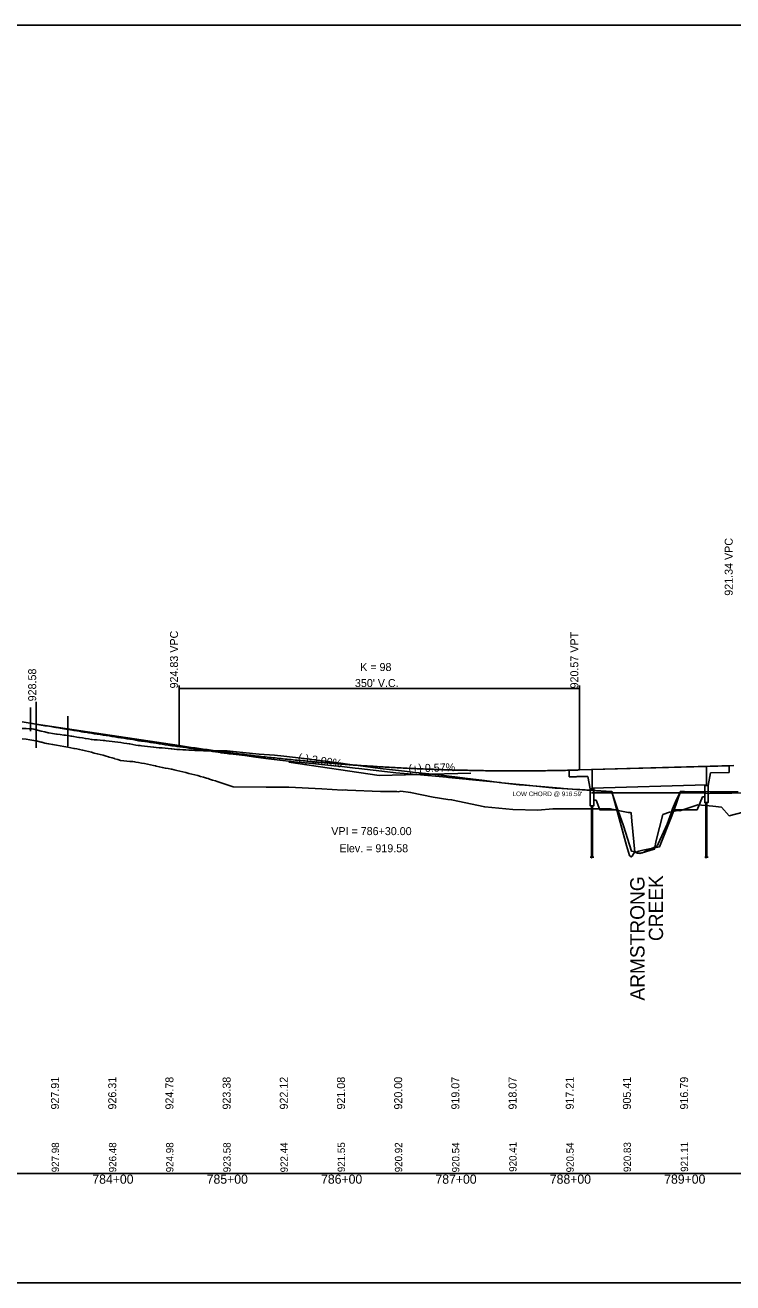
# Model space of a CAD drawing. Extents: x 1558113 to 1562835, y 1129435 to 1135883.
# Drawn here: x 1559817 to 1560436, y 1133348 to 1134448 of the extents above; entities that cross this region are included whole.
import ezdxf

# ---------------------------------------------------------------- set-up
doc = ezdxf.new("R2010")
doc.units = 0
for name, color, linetype in [('BR_CONCRETE', 7, 'Continuous'), ('BR_EXIST_GROUND_LT', 7, 'Continuous'), ('BR_EXIST_GROUND_RT', 7, 'Continuous'), ('BR_GROUND LINES', 7, 'Continuous'), ('BR_USER NOTES', 7, 'Continuous'), ('RD_DDB_GradeTX', 7, 'Continuous'), ('RD_DDB_Profile_EX', 7, 'Continuous'), ('RD_DDB_Profile_Lbl', 7, 'Continuous'), ('RD_DDB_Profile_PR', 7, 'Continuous'), ('RD_DDB_StaTX', 7, 'Continuous'), ('RD_DDB_StripGrade', 7, 'Continuous'), ('RD_DDB_VCLbl', 7, 'Continuous'), ('RD_GPK_Profile_Cell', 7, 'Continuous'), ('RD_SHT_ShtClip', 7, 'Continuous'), ('RD_SHT_TX', 7, 'Continuous')]:
    doc.layers.add(name, color=color, linetype=linetype)

msp = doc.modelspace()

# ---------------------------------------------------------------- linework, layer by layer
at = {"layer": 'BR_CONCRETE'}
for p, q in [((1560292.4, 1133790.6), (1560292.4, 1133796.5)), ((1560301.4, 1133796.7), (1560312.4, 1133797)), ((1560312.4, 1133797), (1560412.4, 1133799.8)), ((1560312.4, 1133780.8), (1560312.4, 1133797)), ((1560412.4, 1133799.8), (1560432.4, 1133800.4)), ((1560412.4, 1133783.6), (1560412.4, 1133799.8)), ((1560413.9, 1133783.2), (1560416.1, 1133794.1)), ((1560416.1, 1133794.1), (1560432.4, 1133794.6)), ((1560432.4, 1133794.6), (1560432.4, 1133800.4)), ((1560301.4, 1133790.9), (1560308.7, 1133791.1)), ((1560310.9, 1133780.3), (1560308.7, 1133791.1)), ((1560312.4, 1133780.8), (1560412.4, 1133783.6)), ((1560311.8, 1133765.3), (1560311.8, 1133720.5)), ((1560312.9, 1133765.3), (1560312.9, 1133720.5)), ((1560411.8, 1133768.2), (1560411.8, 1133720.5)), ((1560412.9, 1133768.2), (1560412.9, 1133720.5))]:
    msp.add_line(p, q, dxfattribs=at)
for points in [[(1560413.9, 1133783.2), (1560410.9, 1133783.2), (1560410.9, 1133768.2), (1560413.9, 1133768.2)], [(1560310.9, 1133780.3), (1560313.9, 1133780.3), (1560313.9, 1133765.3), (1560310.9, 1133765.3)]]:
    msp.add_lwpolyline(points, close=True, dxfattribs=at)
for points in [[(1560310.9, 1133720.5), (1560312, 1133720.5), (1560312, 1133719.8), (1560312.7, 1133721.2), (1560312.7, 1133720.5), (1560313.9, 1133720.5)], [(1560410.9, 1133720.5), (1560412, 1133720.5), (1560412, 1133719.8), (1560412.7, 1133721.2), (1560412.7, 1133720.5), (1560413.9, 1133720.5)]]:
    msp.add_lwpolyline(points, dxfattribs=at)
for points in [[(1560292.4, 1133796.5), (1560295.4, 1133796.5), (1560298.4, 1133796.6), (1560301.4, 1133796.7)], [(1560292.4, 1133790.6), (1560295.4, 1133790.7), (1560298.4, 1133790.8), (1560301.4, 1133790.9)]]:
    msp.add_open_spline(points, degree=2, dxfattribs=at)
at = {"layer": 'BR_EXIST_GROUND_LT'}
msp.add_lwpolyline([(1559814.2, 1133823.9), (1559817.6, 1133823.5), (1559820.9, 1133823.1), (1559824.2, 1133822.6), (1559826.3, 1133822.3), (1559827.5, 1133822), (1559830.8, 1133821.1), (1559831.3, 1133820.9), (1559832.3, 1133820.6), (1559834.1, 1133820.2), (1559835.7, 1133819.8), (1559837.4, 1133819.5), (1559840.8, 1133819), (1559844.1, 1133818.4), (1559847.4, 1133817.8), (1559850.7, 1133817.2), (1559854, 1133816.6), (1559856.6, 1133816.1), (1559859.2, 1133815.6), (1559859.8, 1133815.5), (1559861.8, 1133815.1), (1559864.3, 1133814.6), (1559866.9, 1133814), (1559867.3, 1133813.9), (1559869.5, 1133813.4), (1559872.1, 1133812.8), (1559874.7, 1133812.2), (1559877.2, 1133811.5), (1559879.8, 1133810.9), (1559882.4, 1133810.2), (1559885, 1133809.5), (1559887.6, 1133808.7), (1559889.7, 1133808.1), (1559890.1, 1133808), (1559892.7, 1133807.2), (1559895, 1133806.6), (1559895.3, 1133806.5), (1559897.9, 1133805.7), (1559900, 1133805), (1559900.5, 1133804.9), (1559903.1, 1133804.7), (1559905.6, 1133804.5), (1559908.2, 1133804.2), (1559910.8, 1133804), (1559912.4, 1133803.8), (1559913.4, 1133803.6), (1559916, 1133803.2), (1559918.5, 1133802.7), (1559921.1, 1133802.2), (1559923.7, 1133801.7), (1559926.3, 1133801.2), (1559928.9, 1133800.6), (1559930.7, 1133800.2), (1559931.4, 1133800), (1559934, 1133799.5), (1559936.6, 1133798.9), (1559936.9, 1133798.8), (1559939.2, 1133798.4), (1559941.8, 1133797.9), (1559944.3, 1133797.4), (1559944.9, 1133797.3), (1559946.9, 1133796.8), (1559949.5, 1133796.2), (1559952.1, 1133795.6), (1559954.7, 1133795), (1559957.3, 1133794.4), (1559959.8, 1133793.7), (1559962.4, 1133793.1), (1559965, 1133792.4), (1559967.6, 1133791.7), (1559970.2, 1133791), (1559972.7, 1133790.3), (1559975.3, 1133789.5), (1559976.8, 1133789.1), (1559977.9, 1133788.7), (1559980.5, 1133787.9), (1559983.1, 1133787.1), (1559984.7, 1133786.6), (1559985.6, 1133786.3), (1559988.2, 1133785.5), (1559990.8, 1133784.6), (1559993.4, 1133783.8), (1559996, 1133782.9), (1559998.5, 1133782), (1559998.9, 1133781.9), (1560027.4, 1133781.7), (1560028.9, 1133781.5), (1560045.7, 1133781.6), (1560047.2, 1133781.7), (1560076.2, 1133780.1), (1560094.1, 1133779.1), (1560097, 1133779.2), (1560098.6, 1133779.1), (1560127.5, 1133777.8), (1560141.7, 1133777.8), (1560143, 1133777.7), (1560145.2, 1133778.1), (1560153.7, 1133777.1), (1560173.6, 1133773), (1560186.3, 1133771), (1560189.6, 1133770.6), (1560218.6, 1133764.3), (1560243.1, 1133762), (1560264.9, 1133761.6), (1560278.2, 1133762.7), (1560294.4, 1133762.6), (1560313.8, 1133762.6), (1560328.3, 1133762.7), (1560343.9, 1133759.6), (1560345.8, 1133759.6), (1560346.6, 1133759.3), (1560347.1, 1133751.9), (1560349.8, 1133724.7), (1560352.1, 1133723.8), (1560354.2, 1133723.5), (1560355.9, 1133724.2), (1560358.4, 1133724.9), (1560363.7, 1133726.4), (1560366.9, 1133727.4), (1560368.6, 1133735), (1560374.4, 1133757.6), (1560380, 1133759.9), (1560387.5, 1133761.2), (1560389.1, 1133761), (1560405, 1133766.2), (1560418, 1133764.9), (1560425.6, 1133764.1), (1560432.2, 1133756.6), (1560444.4, 1133759.7)], dxfattribs=at)
at = {"layer": 'BR_EXIST_GROUND_RT'}
msp.add_lwpolyline([(1559814.2, 1133833), (1559817.6, 1133832.9), (1559820.2, 1133832.8), (1559820.9, 1133832.8), (1559822.6, 1133832.7), (1559824.2, 1133832.3), (1559827.5, 1133831.5), (1559830.8, 1133830.7), (1559834.1, 1133829.9), (1559836.9, 1133829.2), (1559837.4, 1133829.1), (1559840.8, 1133828.6), (1559844.1, 1133828.1), (1559844.8, 1133828), (1559847.4, 1133827.6), (1559850.7, 1133827.2), (1559851.9, 1133827), (1559854, 1133826.7), (1559856.6, 1133826.3), (1559857.5, 1133826.2), (1559859.2, 1133825.9), (1559861.8, 1133825.5), (1559863.7, 1133825.2), (1559864.3, 1133825.1), (1559866.9, 1133824.7), (1559869.5, 1133824.2), (1559872.1, 1133823.8), (1559874.7, 1133823.3), (1559875.4, 1133823.2), (1559877.2, 1133823.1), (1559879.8, 1133822.9), (1559882.4, 1133822.7), (1559885, 1133822.5), (1559886.5, 1133822.4), (1559887.6, 1133822.3), (1559890.1, 1133822), (1559892.7, 1133821.6), (1559895.3, 1133821.3), (1559897.9, 1133820.9), (1559900.5, 1133820.6), (1559903.1, 1133820.2), (1559905.6, 1133819.9), (1559907.7, 1133819.6), (1559908.2, 1133819.5), (1559910.8, 1133819), (1559913.4, 1133818.5), (1559915.6, 1133818.1), (1559916, 1133818.1), (1559917.3, 1133818), (1559918.5, 1133817.8), (1559921.1, 1133817.5), (1559923.7, 1133817.2), (1559926.3, 1133816.9), (1559928.9, 1133816.5), (1559929.3, 1133816.5), (1559931.4, 1133816.3), (1559934, 1133816.1), (1559936.6, 1133815.9), (1559939.2, 1133815.7), (1559941.8, 1133815.5), (1559944.3, 1133815.2), (1559945, 1133815.1), (1559946.9, 1133815), (1559947.3, 1133814.9), (1559949.5, 1133814.7), (1559952.1, 1133814.6), (1559954.7, 1133814.4), (1559957.3, 1133814.2), (1559959.8, 1133814.1), (1559962.4, 1133813.9), (1559965, 1133813.8), (1559966.8, 1133813.7), (1559967.6, 1133813.7), (1559970.2, 1133813.6), (1559972.7, 1133813.5), (1559975.3, 1133813.5), (1559977.6, 1133813.4), (1559977.9, 1133813.4), (1559980.5, 1133813.4), (1559983.1, 1133813.3), (1559983.4, 1133813.3), (1559985.6, 1133813.3), (1559988.2, 1133813.3), (1559990.8, 1133813.4), (1559992.2, 1133813.4), (1559993.4, 1133813.3), (1559995, 1133813.1), (1559996, 1133813), (1559997.7, 1133812.9), (1559998.5, 1133812.8), (1560021.3, 1133810.5), (1560034.9, 1133809.5), (1560042.8, 1133808.7), (1560065.6, 1133806), (1560066.2, 1133805.9), (1560066.5, 1133805.9), (1560067.3, 1133805.8), (1560092.7, 1133802.5), (1560100.6, 1133801.5), (1560108, 1133800.6), (1560127.2, 1133798), (1560138, 1133796.8), (1560148.4, 1133795.6), (1560155.3, 1133794.9), (1560172.7, 1133792.9), (1560185.3, 1133791.5), (1560194.7, 1133790.3), (1560201.2, 1133789.5), (1560218.4, 1133787.4), (1560231.2, 1133785.8), (1560241.2, 1133784.6), (1560248.7, 1133783.8), (1560249.5, 1133783.7), (1560253.7, 1133783.4), (1560264, 1133782.5), (1560284.7, 1133780.8), (1560287.6, 1133780.6), (1560299.2, 1133779.7), (1560303.9, 1133779.4), (1560328.7, 1133777.5), (1560329.8, 1133777.3), (1560333.8, 1133765), (1560339.9, 1133747.7), (1560346.9, 1133725.8), (1560347.5, 1133725.6), (1560350.9, 1133724.8), (1560352.9, 1133723.9), (1560356.5, 1133724.2), (1560357.6, 1133724.8), (1560368.3, 1133729.7), (1560368.8, 1133730), (1560369.5, 1133730.7), (1560370.2, 1133732.2), (1560378.1, 1133749.4), (1560381.6, 1133759), (1560382.8, 1133762.7), (1560386.3, 1133770.9), (1560389.4, 1133777), (1560396.1, 1133777.1), (1560400, 1133777.1), (1560403.5, 1133777), (1560404.3, 1133776.9), (1560415.5, 1133776.2), (1560432.1, 1133776.5), (1560434.6, 1133776.5), (1560462.3, 1133776.8)], dxfattribs=at)
at = {"layer": 'BR_GROUND LINES'}
for p, q in [((1560313.9, 1133770.3), (1560315.9, 1133770.3)), ((1560408.9, 1133773.2), (1560410.9, 1133773.2))]:
    msp.add_line(p, q, dxfattribs=at)
for points in [[(1560315.9, 1133770.3), (1560319.3, 1133761.7), (1560334.1, 1133761.7)], [(1560408.9, 1133773.2), (1560404.3, 1133761.7), (1560384.1, 1133761.7)]]:
    msp.add_lwpolyline(points, dxfattribs=at)
at = {"layer": 'BR_USER NOTES'}
for p, q in [((1559821.4, 1133851.4), (1559821.4, 1133830.7)), ((1559826.4, 1133856.4), (1559826.4, 1133815.9)), ((1559821.4, 1133837.6), (1559826.4, 1133836.7)), ((1559854, 1133843.7), (1559854, 1133817.5)), ((1560311.8, 1133776.8), (1560411.8, 1133776.8))]:
    msp.add_line(p, q, dxfattribs=at)
at = {"layer": 'RD_DDB_GradeTX'}
for p in [(1560047.3, 1133803.6), (1560206.3, 1133794)]:
    msp.add_line(p, (1560126.4, 1133791.7), dxfattribs=at)
at = {"layer": 'RD_DDB_Profile_EX'}
msp.add_lwpolyline([(1559814.2, 1133838.7), (1559817.6, 1133838.2), (1559819.3, 1133837.9), (1559820.9, 1133837.6), (1559824.2, 1133837.1), (1559827.5, 1133836.5), (1559830.8, 1133836), (1559834.1, 1133835.4), (1559837.4, 1133834.9), (1559840.8, 1133834.3), (1559841.7, 1133834.2), (1559843.6, 1133833.8), (1559844.1, 1133833.8), (1559847.4, 1133833.2), (1559850.7, 1133832.7), (1559854, 1133832.2), (1559856.6, 1133831.7), (1559859.2, 1133831.3), (1559861.8, 1133830.9), (1559864.3, 1133830.5), (1559866.4, 1133830.1), (1559866.9, 1133830), (1559868.2, 1133829.8), (1559869.5, 1133829.6), (1559872.1, 1133829.2), (1559874.7, 1133828.8), (1559877.2, 1133828.4), (1559879.8, 1133828), (1559882.4, 1133827.6), (1559885, 1133827.2), (1559887.6, 1133826.8), (1559890.1, 1133826.4), (1559891.4, 1133826.2), (1559892.8, 1133825.9), (1559895.3, 1133825.6), (1559897.9, 1133825.2), (1559900.5, 1133824.8), (1559903.1, 1133824.4), (1559905.6, 1133824), (1559908.2, 1133823.6), (1559910.8, 1133823.2), (1559913.4, 1133822.7), (1559916, 1133822.3), (1559918.5, 1133821.9), (1559919, 1133821.8), (1559921.3, 1133821.5), (1559923.7, 1133821.2), (1559926.3, 1133820.8), (1559928.9, 1133820.4), (1559931.4, 1133820), (1559934, 1133819.6), (1559936.6, 1133819.2), (1559939.2, 1133818.8), (1559941.8, 1133818.4), (1559943.4, 1133818.2), (1559944.3, 1133818), (1559945.3, 1133817.9), (1559946.9, 1133817.7), (1559949.5, 1133817.3), (1559952.1, 1133816.9), (1559954.7, 1133816.6), (1559957.3, 1133816.2), (1559959.8, 1133815.8), (1559962.4, 1133815.4), (1559965, 1133815), (1559965.8, 1133814.9), (1559967.6, 1133814.7), (1559970.2, 1133814.3), (1559972.7, 1133814), (1559975.3, 1133813.6), (1559977.9, 1133813.3), (1559980.5, 1133812.9), (1559983.1, 1133812.6), (1559985.6, 1133812.2), (1559987.7, 1133811.9), (1559988.2, 1133811.8), (1559990.8, 1133811.5), (1559993.4, 1133811.1), (1559994.9, 1133810.9), (1559996, 1133810.8), (1559998.5, 1133810.5), (1560008.7, 1133809.2), (1560018.5, 1133807.8), (1560029.6, 1133806.5), (1560042, 1133805), (1560051.9, 1133803.7), (1560067.9, 1133802.2), (1560086.7, 1133800.4), (1560093.6, 1133799.6), (1560105.3, 1133798.3), (1560108.5, 1133797.9), (1560133.6, 1133795.1), (1560138.5, 1133794.5), (1560141, 1133794.3), (1560155.3, 1133793), (1560159.3, 1133792.6), (1560185.3, 1133790.3), (1560186.9, 1133790.2), (1560202.3, 1133788.6), (1560204.8, 1133788.4), (1560232.3, 1133785.7), (1560233.5, 1133785.5), (1560248.9, 1133783.9), (1560250.3, 1133783.8), (1560252.4, 1133783.6), (1560280.3, 1133780.9), (1560281.6, 1133780.9), (1560299.4, 1133779.7), (1560301.8, 1133779.6), (1560329.4, 1133777.8), (1560329.8, 1133777.8), (1560342.5, 1133730.5), (1560345.2, 1133721.8), (1560346.6, 1133720.7), (1560347.4, 1133721.4), (1560349.8, 1133725.3), (1560351, 1133724.9), (1560353.4, 1133725.8), (1560356.7, 1133726.4), (1560359.8, 1133727), (1560371.4, 1133729.6), (1560382.2, 1133756.6), (1560385.7, 1133766), (1560387.3, 1133771.1), (1560389.7, 1133777.9), (1560393.3, 1133777.8), (1560415.7, 1133777.6), (1560418.9, 1133777.6), (1560434.6, 1133777.7), (1560440.2, 1133777.7)], dxfattribs=at)
at = {"layer": 'RD_DDB_Profile_PR'}
for p, q in [((1559826.4, 1133836.7), (1559951.4, 1133818)), ((1560301.4, 1133796.7), (1560436.4, 1133800.5))]:
    msp.add_line(p, q, dxfattribs=at)
msp.add_spline([(1559951.4, 1133818), (1559958.4, 1133816.9), (1559965.4, 1133815.9), (1559972.4, 1133814.9), (1559979.4, 1133814), (1559986.4, 1133813), (1559993.4, 1133812.1), (1560000.4, 1133811.2), (1560007.4, 1133810.4), (1560014.4, 1133809.5), (1560021.4, 1133808.7), (1560028.4, 1133807.9), (1560035.4, 1133807.2), (1560042.4, 1133806.4), (1560049.4, 1133805.7), (1560056.4, 1133805), (1560063.4, 1133804.4), (1560070.4, 1133803.7), (1560077.4, 1133803.1), (1560084.4, 1133802.5), (1560091.4, 1133802), (1560098.4, 1133801.4), (1560105.4, 1133800.9), (1560112.4, 1133800.4), (1560119.4, 1133800), (1560126.4, 1133799.5), (1560133.4, 1133799.1), (1560140.4, 1133798.7), (1560147.4, 1133798.4), (1560154.4, 1133798), (1560161.4, 1133797.7), (1560168.4, 1133797.4), (1560175.4, 1133797.2), (1560182.4, 1133796.9), (1560189.4, 1133796.7), (1560196.4, 1133796.5), (1560203.4, 1133796.4), (1560210.4, 1133796.2), (1560217.4, 1133796.1), (1560224.4, 1133796), (1560231.4, 1133796), (1560238.4, 1133795.9), (1560245.4, 1133795.9), (1560252.4, 1133795.9), (1560259.4, 1133796), (1560266.4, 1133796), (1560273.4, 1133796.1), (1560280.4, 1133796.2), (1560287.4, 1133796.3), (1560294.4, 1133796.5), (1560301.4, 1133796.7)], degree=3, dxfattribs=at)
at = {"layer": 'RD_DDB_VCLbl'}
for p, q in [((1559951.4, 1133870.5), (1559951.4, 1133818)), ((1560301.4, 1133870.5), (1560301.4, 1133796.7)), ((1559951.4, 1133868), (1560301.4, 1133868))]:
    msp.add_line(p, q, dxfattribs=at)
at = {"layer": 'RD_GPK_Profile_Cell'}
msp.add_line((1558196.4, 1133443.8), (1562834.7, 1133443.8), dxfattribs=at)
at = {"layer": 'RD_SHT_ShtClip'}
msp.add_lwpolyline([(1559525.2, 1134448.1), (1561325.2, 1134448.1), (1561325.2, 1133348.1), (1559525.2, 1133348.1)], close=True, dxfattribs=at)

# ---------------------------------------------------------------- texts
at = {"layer": 'BR_CONCRETE'}
for p in [(1560313.1, 1133792.6), (1560410.4, 1133793.9)]:
    msp.add_text('F', height=0.0521, rotation=0, dxfattribs=at).set_placement(p)
at = {"layer": 'BR_USER NOTES'}
msp.add_text("LOW CHORD @ 916.59'", height=4, dxfattribs=at).set_placement((1560242.9, 1133773.8))
at = {"layer": 'RD_DDB_GradeTX'}
for s, rotation, p in [('(-) 3.00%', 351.4692, (1560055.1, 1133804.4)), ('(+) 0.57%', 1.6246, (1560152, 1133794.5))]:
    msp.add_text(s, height=7, rotation=rotation, dxfattribs=at).set_placement(p)
at = {"layer": 'RD_DDB_Profile_Lbl'}
msp.add_text('928.58', height=7, rotation=90, dxfattribs=at).set_placement((1559826.4, 1133856.7))
for s, p in [('VPI = 786+30.00', (1560084.4, 1133739.7)), ('Elev. = 919.58', (1560091.5, 1133724.7))]:
    msp.add_text(s, height=7, dxfattribs=at).set_placement(p)
at = {"layer": 'RD_DDB_StaTX'}
for s, p in [('784+00', (1559875.5, 1133434.8)), ('785+00', (1559975.5, 1133434.8)), ('786+00', (1560075.5, 1133434.8)), ('787+00', (1560175.5, 1133434.8)), ('788+00', (1560275.5, 1133434.8)), ('789+00', (1560375.5, 1133434.8))]:
    msp.add_text(s, height=8, dxfattribs=at).set_placement(p)
at = {"layer": 'RD_DDB_StripGrade'}
for s, height, p in [('921.34 VPC', 7, (1560435.4, 1133949.1)), ('924.83 VPC', 7, (1559950.4, 1133868)), ('920.57 VPT', 7, (1560300.4, 1133868)), ('927.91', 7, (1559846.4, 1133499.7)), ('926.31', 7, (1559896.4, 1133499.7)), ('924.78', 7, (1559946.4, 1133499.7)), ('923.38', 7, (1559996.4, 1133499.7)), ('922.12', 7, (1560046.4, 1133499.7)), ('921.08', 7, (1560096.4, 1133499.7)), ('920.00', 7, (1560146.4, 1133499.7)), ('919.07', 7, (1560196.4, 1133499.7)), ('918.07', 7, (1560246.4, 1133499.7)), ('917.21', 7, (1560296.4, 1133499.7)), ('905.41', 7, (1560346.4, 1133499.7)), ('916.79', 7, (1560396.4, 1133499.7)), ('927.98', 6.4, (1559846.4, 1133444.8)), ('926.48', 6.4, (1559896.4, 1133444.8)), ('924.98', 6.4, (1559946.4, 1133444.8)), ('923.58', 6.4, (1559996.4, 1133444.8)), ('922.44', 6.4, (1560046.4, 1133444.7)), ('921.55', 6.4, (1560096.4, 1133444.9)), ('920.92', 6.4, (1560146.4, 1133444.8)), ('920.54', 6.4, (1560196.4, 1133444.7)), ('920.41', 6.4, (1560246.4, 1133445.2)), ('920.54', 6.4, (1560296.4, 1133444.7)), ('920.83', 6.4, (1560346.4, 1133445)), ('921.11', 6.4, (1560396.4, 1133445.2))]:
    msp.add_text(s, height=height, rotation=90, dxfattribs=at).set_placement(p)
at = {"layer": 'RD_DDB_VCLbl'}
for s, p in [('K = 98', (1560109.7, 1133883.2)), ("350' V.C.", (1560105.1, 1133869.2))]:
    msp.add_text(s, height=7, dxfattribs=at).set_placement(p)
at = {"layer": 'RD_SHT_TX'}
for s, p in [(' CREEK', (1560374.5, 1133642.4)), ('ARMSTRONG', (1560358.3, 1133595))]:
    msp.add_text(s, height=12.5, rotation=90, dxfattribs=at).set_placement(p)

doc.saveas('drawing.dxf')
